// Mitsubishi GX Works2 project: FX3G_COM3_RS   PLC: FX3G

PROGRAM MAIN
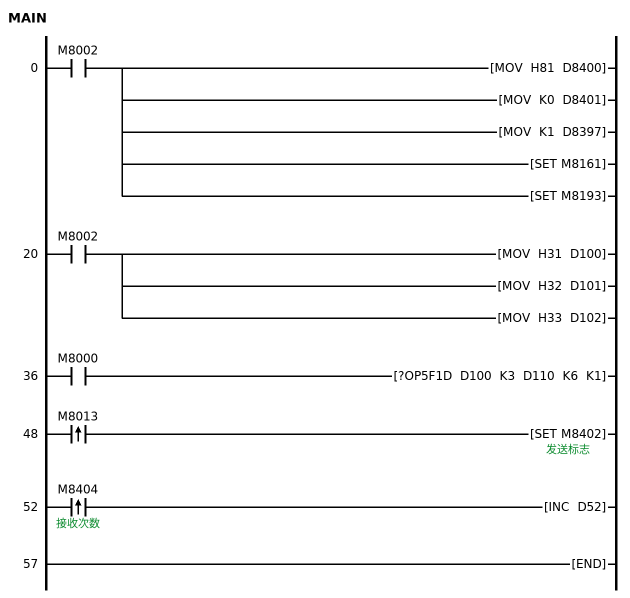
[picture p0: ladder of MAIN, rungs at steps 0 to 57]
0     LD      M8002
      MOV     H81 D8400
        [note] 通讯设定9600 8 N 1
      MOV     K0 D8401
        [note] RS协议
      MOV     K1 D8397
        [note] 串口3切换
      SET     M8161
        [note] on：8位模式off:16位模式
      SET     M8193
        [note] on:其他协议协议off:编程口协议
20    LD      M8002
      MOV     H31 D100
      MOV     H32 D101
      MOV     H33 D102
36    LD      M8000
      ?OP5F1D D100 K3 D110 K6 K1
48    LDP     M8013
      SET     M8402  ; 发送标志
52    LDP     M8404  ; 接收次数
      INC     D52
57    END
END_PROGRAM

// device comments not shown above
D200  ; 写入数量，1个
D211  ; 转速
M2  ; 反转
M3  ; 停止
